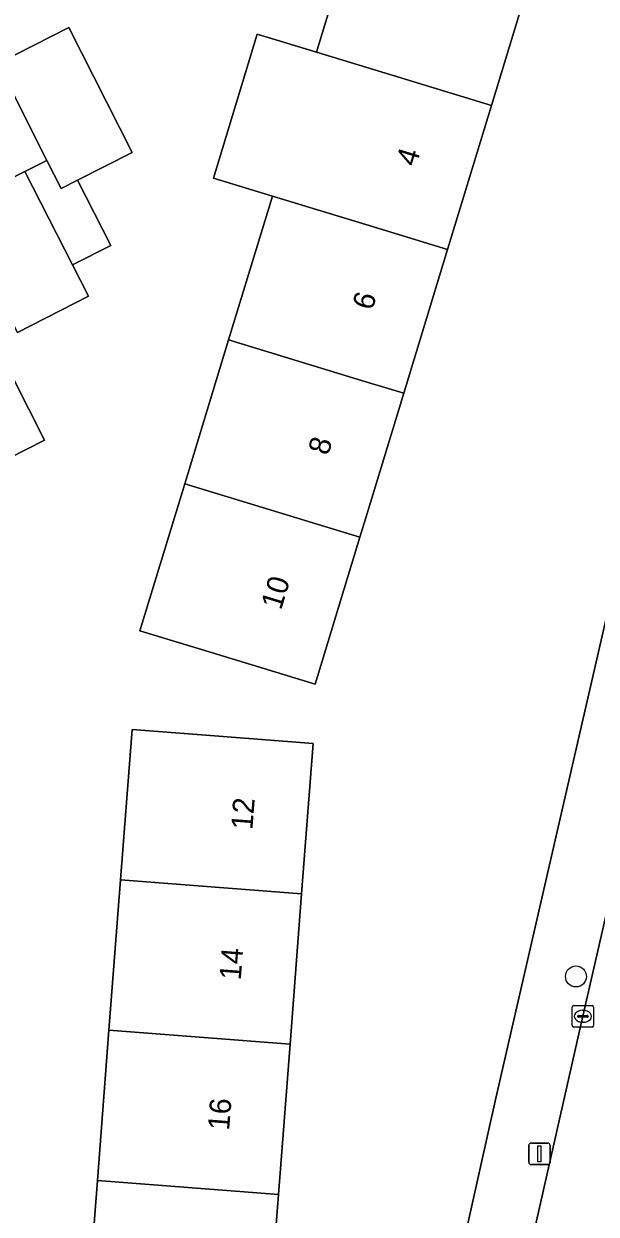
# Model space of a CAD drawing. Extents: x 161838 to 162344, y 381620 to 382160.
# Drawn here: x 161984.1 to 162010.7, y 381833 to 381888.5 of the extents above; entities that cross this region are included whole.
import ezdxf

# ---------------------------------------------------------------- set-up
doc = ezdxf.new("R2010")
doc.units = 0
for name, color, linetype in [('IMGEO_Boom', 7, 'Continuous'), ('IMGEO_Erf', 7, 'Continuous'), ('IMGEO_Kolk', 7, 'Continuous'), ('IMGEO_Lichtmast', 7, 'Continuous'), ('IMGEO_Pand', 7, 'Continuous'), ('IMGEO_Pand_nummerreeks', 7, 'Continuous'), ('IMGEO_Rijbaan_lokaal_open', 7, 'Continuous'), ('IMGEO_Voetpad_open', 7, 'Continuous')]:
    doc.layers.add(name, color=color, linetype=linetype)

msp = doc.modelspace()

# ---------------------------------------------------------------- linework, layer by layer
at = {"layer": 'IMGEO_Boom'}
msp.add_circle((162009.795, 381844.099), 0.489, dxfattribs=at)
at = {"layer": 'IMGEO_Erf'}
for points in [[(162007.941, 381891.591), (162005.854, 381884.732), (162003.812, 381878.019), (162001.77, 381871.307), (162000, 381865.487), (161999.728, 381864.594), (161997.641, 381857.738), (161992.858, 381859.195), (161989.473, 381860.226), (161991.561, 381867.081), (161993.605, 381873.792), (161995.65, 381880.504), (161992.895, 381881.343), (161994.938, 381888.055), (161997.695, 381887.216), (161999.681, 381893.737)], [(161993.909, 381784.124), (162000, 381811.259), (162006.057, 381838.422), (162012.585, 381866.816)], [(161986.949, 381827.572), (161987.489, 381834.583), (161988.03, 381841.595), (161988.571, 381848.605), (161989.112, 381855.615), (161992.538, 381855.351), (161997.552, 381854.964), (161997.011, 381847.955), (161996.47, 381840.945), (161995.929, 381833.933), (161995.389, 381826.922)]]:
    msp.add_lwpolyline(points, dxfattribs=at)
for points in [[(161980.803, 381879.971), (161984.112, 381881.652), (161985.136, 381882.172), (161982.845, 381886.683), (161986.154, 381888.364), (161989.111, 381882.541), (161986.566, 381881.248), (161988.112, 381878.205), (161986.324, 381877.296), (161987.069, 381875.829), (161983.76, 381874.148)], [(161981.717, 381867.436), (161978.76, 381873.259), (161982.069, 381874.94), (161985.026, 381869.117)]]:
    msp.add_lwpolyline(points, close=True, dxfattribs=at)
at = {"layer": 'IMGEO_Kolk'}
for p, q in [((162009.617, 381841.813), (162009.617, 381842.665)), ((162009.692, 381842.739), (162010.544, 381842.739)), ((162010.105, 381842.519), (162010.13, 381842.519)), ((162010.618, 381842.665), (162010.618, 381841.813)), ((162009.876, 381842.233), (162009.876, 381842.245)), ((162010.314, 381842.196), (162009.916, 381842.196)), ((162009.919, 381842.282), (162010.317, 381842.282)), ((162010.128, 381841.959), (162010.103, 381841.959)), ((162010.36, 381842.245), (162010.36, 381842.233)), ((162010.544, 381841.739), (162009.692, 381841.739))]:
    msp.add_line(p, q, dxfattribs=at)
for points in [[(162009.617, 381841.813), (162009.617, 381842.665)], [(162009.692, 381842.739), (162010.544, 381842.739)], [(162010.618, 381842.665), (162010.618, 381841.813)], [(162010.544, 381841.739), (162009.692, 381841.739)]]:
    msp.add_lwpolyline(points, dxfattribs=at)
for centre, radius, start, end in [((162009.694, 381842.663), 0.0765, 91.552, 178.448), ((162009.694, 381842.663), 0.0765, 91.552, 178.448), ((162010.542, 381842.663), 0.0765, 1.552, 88.448), ((162010.542, 381842.663), 0.0765, 1.552, 88.448), ((162009.694, 381841.815), 0.0765, 181.552, 268.448), ((162009.694, 381841.815), 0.0765, 181.552, 268.448), ((162009.916, 381842.242), 0.0403, 85.8775, 175.7526), ((162009.913, 381842.232), 0.0366, 178.938, 274.7102), ((162010.317, 381842.239), 0.043, 264.8664, 352.4533), ((162010.321, 381842.244), 0.0386, 1.7309, 96.639), ((162010.542, 381841.815), 0.0765, 271.552, 358.448), ((162010.542, 381841.815), 0.0765, 271.552, 358.448)]:
    msp.add_arc(centre, radius, start, end, dxfattribs=at)
for centre, major_axis, ratio, start_param, end_param in [((162010.104, 381842.239), (-0.387, 0.002), 0.722429, 4.712389, 7.853982), ((162010.129, 381842.239), (-0.39, 0.002), 0.717154, 1.570796, 4.712389)]:
    msp.add_ellipse(centre, major_axis=major_axis, ratio=ratio, start_param=start_param, end_param=end_param, dxfattribs=at)
at = {"layer": 'IMGEO_Lichtmast'}
for p, q in [((162007.596, 381835.426), (162007.596, 381836.226)), ((162007.596, 381836.226), (162007.596, 381835.426)), ((162007.696, 381836.326), (162008.486, 381836.326)), ((162008.486, 381836.326), (162007.696, 381836.326)), ((162008.586, 381836.226), (162008.586, 381835.426)), ((162008.586, 381835.426), (162008.586, 381836.226)), ((162008.486, 381835.326), (162007.696, 381835.326)), ((162007.696, 381835.326), (162008.486, 381835.326))]:
    msp.add_line(p, q, dxfattribs=at)
msp.add_lwpolyline([(162008.016, 381836.201), (162008.166, 381836.201), (162008.166, 381835.451), (162008.016, 381835.451), (162008.016, 381836.201)], dxfattribs=at)
for centre, start, end in [((162007.696, 381836.226), 90, 180), ((162007.696, 381836.226), 90, 180), ((162008.486, 381836.226), 0, 90), ((162008.486, 381836.226), 360, 90), ((162007.696, 381835.426), 180, 270), ((162007.696, 381835.426), 180, 270), ((162008.486, 381835.426), 270, 0), ((162008.486, 381835.426), 270, 0)]:
    msp.add_arc(centre, 0.1, start, end, dxfattribs=at)
at = {"layer": 'IMGEO_Pand'}
for points in [[(161997.86, 381896.255), (161999.681, 381893.737), (161997.695, 381887.216), (162000, 381886.514), (162005.854, 381884.732), (162007.941, 381891.591), (162005.97, 381892.19), (162006.744, 381894.733), (162003.176, 381899.912), (162000, 381897.727)], [(161986.154, 381888.364), (161982.845, 381886.683), (161985.136, 381882.172), (161985.802, 381880.86), (161986.566, 381881.248), (161989.111, 381882.541)], [(162003.812, 381878.019), (162005.854, 381884.732), (162000, 381886.514), (161997.695, 381887.216), (161994.938, 381888.055), (161992.895, 381881.343), (161995.65, 381880.504), (162000, 381879.18)], [(161986.566, 381881.248), (161985.802, 381880.86), (161985.136, 381882.172), (161984.112, 381881.652), (161986.324, 381877.296), (161988.112, 381878.205)], [(161984.112, 381881.652), (161980.803, 381879.971), (161983.76, 381874.148), (161987.069, 381875.829), (161986.324, 381877.296)], [(162001.77, 381871.307), (162003.812, 381878.019), (162000, 381879.18), (161995.65, 381880.504), (161993.605, 381873.792), (162000, 381871.846)], [(161981.717, 381867.436), (161985.026, 381869.117), (161982.069, 381874.94), (161978.76, 381873.259)], [(162001.77, 381871.307), (162000, 381871.846), (161993.605, 381873.792), (161991.561, 381867.081), (161999.728, 381864.594), (162000, 381865.487)], [(161991.561, 381867.081), (161989.473, 381860.226), (161992.858, 381859.195), (161997.641, 381857.738), (161999.728, 381864.594)], [(161997.011, 381847.955), (161997.552, 381854.964), (161992.538, 381855.351), (161989.112, 381855.615), (161988.571, 381848.605)], [(161988.03, 381841.595), (161996.47, 381840.945), (161997.011, 381847.955), (161988.571, 381848.605)], [(161988.03, 381841.595), (161987.489, 381834.583), (161995.929, 381833.933), (161996.47, 381840.945)], [(161995.389, 381826.922), (161995.929, 381833.933), (161987.489, 381834.583), (161986.949, 381827.572)]]:
    msp.add_lwpolyline(points, close=True, dxfattribs=at)
at = {"layer": 'IMGEO_Rijbaan_lokaal_open'}
msp.add_lwpolyline([(162017.975, 381876.532), (162010.118, 381842.239), (161997.168, 381785.034)], dxfattribs=at)
at = {"layer": 'IMGEO_Voetpad_open'}
for points in [[(162016.258, 381885.569), (162005.739, 381900.791), (162004.132, 381899.684), (162004.242, 381899.525), (162013.985, 381885.418), (162015.122, 381883.128), (162015.619, 381881.528), (162015.663, 381880.219), (162015.506, 381878.919), (162012.585, 381866.816), (162006.057, 381838.422), (162000, 381811.259), (161993.909, 381784.124)], [(162010.118, 381842.239), (162017.975, 381876.532)], [(161997.168, 381785.034), (162010.118, 381842.239)]]:
    msp.add_lwpolyline(points, dxfattribs=at)

# ---------------------------------------------------------------- texts
at = {"layer": 'IMGEO_Pand_nummerreeks'}
for s, rotation, p in [('4', 73.081, (162002.343, 381881.845)), ('6', 73.0786, (162000.302, 381875.134)), ('8', 73.0773, (161998.242, 381868.368)), ('10', 73.0773, (161996.048, 381861.156)), ('12', 85.5884, (161994.712, 381850.916)), ('14', 85.5884, (161994.171, 381843.907)), ('16', 85.5884, (161993.63, 381836.896))]:
    msp.add_text(s, height=1, rotation=rotation, dxfattribs=at).set_placement(p)

doc.saveas('drawing.dxf')
